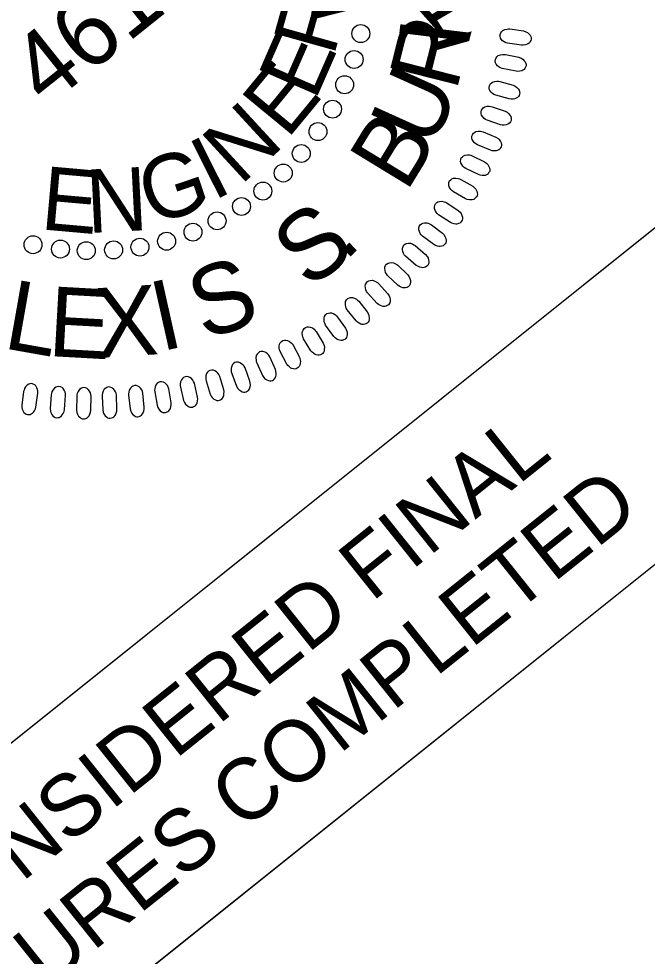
# Model space of a CAD drawing. Extents: x 473546 to 475544, y 505920 to 507827.
# Drawn here: x 474878.2 to 474934.4, y 507600.7 to 507684.5 of the extents above; entities that cross this region are included whole.
import ezdxf

# ---------------------------------------------------------------- set-up
doc = ezdxf.new("R2010")
doc.units = 0
for name, color, linetype in [('Sheet Clip Boundary CELL', 7, 'Continuous'), ('Sheet Plan CELL', 7, 'Continuous'), ('Sheet Profile Grid Minor CELL', 7, 'Continuous'), ('Sheet Sticker Exception Certification CELL', 7, 'Continuous'), ('Sheet Sticker Incomplete CELL', 7, 'Continuous')]:
    doc.layers.add(name, color=color, linetype=linetype)

msp = doc.modelspace()

# ---------------------------------------------------------------- linework, layer by layer
at = {"layer": 'Sheet Clip Boundary CELL'}
msp.add_lwpolyline([(474813.139, 507538.121), (474704.643, 507673.668), (473746.994, 506907.144), (474401.701, 506086.253), (475384.175, 506871.789), (475333.837, 506934.746), (475466.728, 507040.999), (474969.31, 507663.123)], close=True, dxfattribs=at)
at = {"layer": 'Sheet Plan CELL'}
msp.add_lwpolyline([(474806.271, 507706.801), (474884.328, 507769.288), (474954.641, 507681.452), (474876.574, 507618.957)], close=True, dxfattribs=at)
at = {"layer": 'Sheet Profile Grid Minor CELL'}
for points in [[(474922.094, 507683.546), (474923.309, 507683.372), (474923.52, 507683.303), (474923.652, 507683.232), (474923.803, 507683.097), (474923.898, 507682.985), (474923.961, 507682.863), (474923.986, 507682.754), (474923.989, 507682.639), (474923.954, 507682.532), (474923.907, 507682.418), (474923.834, 507682.322), (474923.72, 507682.233), (474923.632, 507682.185), (474923.475, 507682.14), (474923.288, 507682.106), (474923.128, 507682.106), (474921.882, 507682.277), (474921.718, 507682.323), (474921.586, 507682.388), (474921.441, 507682.499), (474921.318, 507682.629), (474921.254, 507682.737), (474921.216, 507682.901), (474921.218, 507683.052), (474921.278, 507683.194), (474921.343, 507683.29), (474921.459, 507683.402), (474921.643, 507683.497), (474921.831, 507683.538), (474921.963, 507683.549)], [(474921.697, 507681.269), (474922.898, 507681.019), (474923.105, 507680.938), (474923.231, 507680.858), (474923.375, 507680.714), (474923.462, 507680.597), (474923.518, 507680.47), (474923.535, 507680.36), (474923.532, 507680.246), (474923.489, 507680.141), (474923.436, 507680.03), (474923.356, 507679.939), (474923.237, 507679.857), (474923.147, 507679.814), (474922.987, 507679.779), (474922.798, 507679.757), (474922.638, 507679.768), (474921.406, 507680.016), (474921.245, 507680.073), (474921.117, 507680.146), (474920.979, 507680.266), (474920.865, 507680.403), (474920.807, 507680.515), (474920.78, 507680.681), (474920.791, 507680.831), (474920.861, 507680.969), (474920.931, 507681.062), (474921.055, 507681.166), (474921.245, 507681.248), (474921.435, 507681.278), (474921.568, 507681.281)], [(474921.187, 507678.855), (474922.37, 507678.53), (474922.571, 507678.436), (474922.693, 507678.35), (474922.826, 507678.197), (474922.906, 507678.073), (474922.954, 507677.944), (474922.964, 507677.833), (474922.953, 507677.719), (474922.905, 507677.617), (474922.844, 507677.509), (474922.76, 507677.424), (474922.635, 507677.35), (474922.542, 507677.313), (474922.38, 507677.287), (474922.191, 507677.278), (474922.032, 507677.298), (474920.818, 507677.623), (474920.66, 507677.69), (474920.538, 507677.771), (474920.407, 507677.899), (474920.302, 507678.044), (474920.251, 507678.159), (474920.235, 507678.326), (474920.256, 507678.476), (474920.334, 507678.609), (474920.409, 507678.697), (474920.539, 507678.793), (474920.734, 507678.863), (474920.926, 507678.881), (474921.058, 507678.875)], [(474920.499, 507676.604), (474921.66, 507676.205), (474921.855, 507676.099), (474921.97, 507676.004), (474922.094, 507675.843), (474922.167, 507675.715), (474922.205, 507675.583), (474922.21, 507675.471), (474922.192, 507675.358), (474922.136, 507675.259), (474922.069, 507675.156), (474921.979, 507675.076), (474921.851, 507675.01), (474921.756, 507674.979), (474921.592, 507674.964), (474921.402, 507674.965), (474921.245, 507674.996), (474920.054, 507675.397), (474919.901, 507675.473), (474919.783, 507675.561), (474919.661, 507675.698), (474919.566, 507675.849), (474919.522, 507675.967), (474919.516, 507676.135), (474919.546, 507676.283), (474919.632, 507676.412), (474919.714, 507676.494), (474919.849, 507676.582), (474920.048, 507676.64), (474920.24, 507676.646), (474920.372, 507676.631)], [(474919.708, 507674.362), (474920.841, 507673.891), (474921.029, 507673.773), (474921.138, 507673.671), (474921.252, 507673.502), (474921.316, 507673.37), (474921.346, 507673.236), (474921.343, 507673.124), (474921.318, 507673.013), (474921.257, 507672.917), (474921.184, 507672.818), (474921.089, 507672.744), (474920.956, 507672.686), (474920.859, 507672.661), (474920.695, 507672.656), (474920.507, 507672.67), (474920.351, 507672.711), (474919.188, 507673.186), (474919.04, 507673.271), (474918.928, 507673.367), (474918.815, 507673.51), (474918.729, 507673.667), (474918.692, 507673.788), (474918.697, 507673.956), (474918.736, 507674.102), (474918.83, 507674.224), (474918.917, 507674.302), (474919.057, 507674.381), (474919.26, 507674.426), (474919.452, 507674.42), (474919.582, 507674.397)], [(474918.731, 507672.218), (474919.833, 507671.677), (474920.013, 507671.547), (474920.115, 507671.439), (474920.219, 507671.263), (474920.274, 507671.128), (474920.296, 507670.992), (474920.286, 507670.88), (474920.254, 507670.77), (474920.187, 507670.679), (474920.107, 507670.585), (474920.008, 507670.517), (474919.872, 507670.468), (474919.774, 507670.448), (474919.61, 507670.454), (474919.423, 507670.48), (474919.269, 507670.53), (474918.138, 507671.077), (474917.996, 507671.172), (474917.89, 507671.274), (474917.787, 507671.424), (474917.711, 507671.586), (474917.682, 507671.709), (474917.697, 507671.876), (474917.746, 507672.02), (474917.847, 507672.136), (474917.938, 507672.208), (474918.083, 507672.278), (474918.288, 507672.311), (474918.48, 507672.292), (474918.609, 507672.261)], [(474917.7, 507670.102), (474918.764, 507669.493), (474918.936, 507669.352), (474919.032, 507669.237), (474919.124, 507669.056), (474919.17, 507668.917), (474919.184, 507668.78), (474919.167, 507668.669), (474919.128, 507668.562), (474919.055, 507668.475), (474918.97, 507668.386), (474918.866, 507668.324), (474918.728, 507668.283), (474918.629, 507668.271), (474918.465, 507668.286), (474918.28, 507668.324), (474918.13, 507668.383), (474917.036, 507669.001), (474916.9, 507669.104), (474916.801, 507669.212), (474916.706, 507669.369), (474916.641, 507669.536), (474916.62, 507669.66), (474916.645, 507669.826), (474916.703, 507669.966), (474916.811, 507670.076), (474916.907, 507670.142), (474917.056, 507670.203), (474917.262, 507670.222), (474917.453, 507670.192), (474917.579, 507670.153)], [(474916.447, 507667.999), (474917.471, 507667.325), (474917.634, 507667.173), (474917.722, 507667.053), (474917.802, 507666.866), (474917.84, 507666.724), (474917.845, 507666.586), (474917.821, 507666.477), (474917.775, 507666.372), (474917.697, 507666.29), (474917.607, 507666.207), (474917.499, 507666.152), (474917.358, 507666.12), (474917.259, 507666.113), (474917.097, 507666.139), (474916.914, 507666.188), (474916.768, 507666.257), (474915.715, 507666.941), (474915.586, 507667.054), (474915.494, 507667.168), (474915.41, 507667.33), (474915.355, 507667.5), (474915.342, 507667.626), (474915.378, 507667.79), (474915.443, 507667.926), (474915.558, 507668.028), (474915.658, 507668.088), (474915.811, 507668.14), (474916.018, 507668.146), (474916.206, 507668.104), (474916.33, 507668.058)], [(474915.076, 507666.043), (474916.057, 507665.305), (474916.21, 507665.144), (474916.29, 507665.018), (474916.358, 507664.826), (474916.388, 507664.683), (474916.384, 507664.545), (474916.353, 507664.438), (474916.301, 507664.336), (474916.218, 507664.259), (474916.122, 507664.181), (474916.012, 507664.133), (474915.869, 507664.109), (474915.77, 507664.11), (474915.609, 507664.146), (474915.43, 507664.206), (474915.289, 507664.284), (474914.28, 507665.033), (474914.158, 507665.153), (474914.074, 507665.273), (474914, 507665.441), (474913.956, 507665.614), (474913.95, 507665.74), (474913.997, 507665.901), (474914.071, 507666.033), (474914.193, 507666.128), (474914.296, 507666.181), (474914.451, 507666.224), (474914.659, 507666.217), (474914.843, 507666.163), (474914.964, 507666.109)], [(474913.628, 507664.195), (474914.56, 507663.396), (474914.703, 507663.226), (474914.775, 507663.096), (474914.831, 507662.9), (474914.851, 507662.755), (474914.839, 507662.617), (474914.801, 507662.512), (474914.743, 507662.414), (474914.655, 507662.342), (474914.555, 507662.271), (474914.441, 507662.23), (474914.297, 507662.215), (474914.198, 507662.221), (474914.041, 507662.268), (474913.865, 507662.339), (474913.729, 507662.425), (474912.77, 507663.237), (474912.656, 507663.364), (474912.578, 507663.489), (474912.516, 507663.661), (474912.482, 507663.836), (474912.485, 507663.963), (474912.541, 507664.12), (474912.624, 507664.247), (474912.751, 507664.334), (474912.857, 507664.382), (474913.015, 507664.414), (474913.222, 507664.394), (474913.403, 507664.329), (474913.52, 507664.267)], [(474912.077, 507662.427), (474912.957, 507661.573), (474913.089, 507661.394), (474913.153, 507661.259), (474913.197, 507661.06), (474913.207, 507660.914), (474913.187, 507660.778), (474913.142, 507660.675), (474913.078, 507660.58), (474912.986, 507660.514), (474912.881, 507660.449), (474912.766, 507660.415), (474912.621, 507660.41), (474912.522, 507660.423), (474912.367, 507660.479), (474912.197, 507660.561), (474912.067, 507660.656), (474911.16, 507661.525), (474911.054, 507661.66), (474910.986, 507661.789), (474910.934, 507661.965), (474910.911, 507662.142), (474910.922, 507662.268), (474910.988, 507662.422), (474911.078, 507662.544), (474911.211, 507662.622), (474911.32, 507662.663), (474911.479, 507662.685), (474911.684, 507662.652), (474911.861, 507662.575), (474911.974, 507662.507)], [(474910.351, 507660.798), (474911.176, 507659.889), (474911.296, 507659.702), (474911.352, 507659.564), (474911.382, 507659.363), (474911.385, 507659.216), (474911.355, 507659.082), (474911.304, 507658.982), (474911.235, 507658.892), (474911.138, 507658.832), (474911.03, 507658.773), (474910.912, 507658.747), (474910.767, 507658.751), (474910.669, 507658.769), (474910.519, 507658.835), (474910.354, 507658.928), (474910.23, 507659.031), (474909.379, 507659.956), (474909.282, 507660.096), (474909.222, 507660.23), (474909.181, 507660.408), (474909.17, 507660.587), (474909.188, 507660.711), (474909.264, 507660.861), (474909.362, 507660.977), (474909.499, 507661.047), (474909.61, 507661.081), (474909.771, 507661.093), (474909.974, 507661.047), (474910.144, 507660.96), (474910.253, 507660.884)], [(474908.58, 507659.223), (474909.346, 507658.265), (474909.453, 507658.071), (474909.5, 507657.929), (474909.519, 507657.726), (474909.511, 507657.58), (474909.473, 507657.447), (474909.417, 507657.351), (474909.341, 507657.266), (474909.242, 507657.211), (474909.129, 507657.16), (474909.01, 507657.14), (474908.866, 507657.154), (474908.769, 507657.179), (474908.624, 507657.253), (474908.465, 507657.356), (474908.348, 507657.467), (474907.557, 507658.443), (474907.469, 507658.59), (474907.417, 507658.727), (474907.387, 507658.907), (474907.387, 507659.086), (474907.413, 507659.21), (474907.499, 507659.355), (474907.603, 507659.464), (474907.745, 507659.526), (474907.858, 507659.552), (474908.019, 507659.554), (474908.218, 507659.496), (474908.383, 507659.397), (474908.487, 507659.315)], [(474906.698, 507657.809), (474907.402, 507656.804), (474907.497, 507656.604), (474907.535, 507656.459), (474907.541, 507656.256), (474907.525, 507656.11), (474907.478, 507655.981), (474907.416, 507655.888), (474907.334, 507655.807), (474907.232, 507655.76), (474907.117, 507655.715), (474906.997, 507655.704), (474906.854, 507655.726), (474906.759, 507655.756), (474906.618, 507655.84), (474906.466, 507655.953), (474906.356, 507656.071), (474905.628, 507657.095), (474905.549, 507657.246), (474905.506, 507657.387), (474905.488, 507657.569), (474905.499, 507657.747), (474905.533, 507657.869), (474905.627, 507658.008), (474905.738, 507658.11), (474905.884, 507658.163), (474905.997, 507658.182), (474906.159, 507658.174), (474906.354, 507658.103), (474906.513, 507657.995), (474906.611, 507657.906)], [(474904.765, 507656.515), (474905.405, 507655.468), (474905.487, 507655.262), (474905.516, 507655.115), (474905.509, 507654.912), (474905.483, 507654.768), (474905.429, 507654.641), (474905.361, 507654.553), (474905.275, 507654.477), (474905.17, 507654.436), (474905.052, 507654.399), (474904.931, 507654.395), (474904.79, 507654.426), (474904.697, 507654.463), (474904.562, 507654.556), (474904.417, 507654.677), (474904.315, 507654.801), (474903.653, 507655.869), (474903.584, 507656.026), (474903.549, 507656.169), (474903.542, 507656.351), (474903.565, 507656.529), (474903.606, 507656.648), (474903.709, 507656.781), (474903.826, 507656.876), (474903.974, 507656.92), (474904.09, 507656.932), (474904.25, 507656.913), (474904.44, 507656.831), (474904.592, 507656.713), (474904.685, 507656.617)], [(474902.714, 507655.291), (474903.287, 507654.206), (474903.357, 507653.995), (474903.376, 507653.847), (474903.356, 507653.645), (474903.321, 507653.503), (474903.259, 507653.38), (474903.185, 507653.295), (474903.095, 507653.226), (474902.987, 507653.191), (474902.867, 507653.161), (474902.747, 507653.165), (474902.608, 507653.205), (474902.518, 507653.247), (474902.388, 507653.348), (474902.251, 507653.479), (474902.157, 507653.609), (474901.564, 507654.717), (474901.504, 507654.878), (474901.479, 507655.022), (474901.483, 507655.205), (474901.517, 507655.381), (474901.566, 507655.497), (474901.676, 507655.622), (474901.8, 507655.71), (474901.95, 507655.744), (474902.066, 507655.749), (474902.225, 507655.721), (474902.41, 507655.627), (474902.554, 507655.499), (474902.64, 507655.399)], [(474899.472, 507653.706), (474899.976, 507652.587), (474900.1, 507652.403), (474900.205, 507652.296), (474900.377, 507652.188), (474900.511, 507652.127), (474900.646, 507652.101), (474900.757, 507652.107), (474900.868, 507652.136), (474900.961, 507652.2), (474901.059, 507652.277), (474901.13, 507652.373), (474901.184, 507652.508), (474901.206, 507652.605), (474901.205, 507652.769), (474901.186, 507652.957), (474901.141, 507653.112), (474900.632, 507654.261), (474900.542, 507654.406), (474900.443, 507654.515), (474900.296, 507654.624), (474900.137, 507654.705), (474900.015, 507654.738), (474899.847, 507654.728), (474899.703, 507654.684), (474899.583, 507654.586), (474899.508, 507654.498), (474899.433, 507654.355), (474899.394, 507654.151), (474899.406, 507653.96), (474899.432, 507653.83)], [(474897.23, 507652.773), (474897.663, 507651.625), (474897.775, 507651.433), (474897.873, 507651.321), (474898.038, 507651.201), (474898.168, 507651.133), (474898.301, 507651.098), (474898.412, 507651.098), (474898.525, 507651.119), (474898.622, 507651.177), (474898.724, 507651.247), (474898.801, 507651.34), (474898.863, 507651.471), (474898.891, 507651.566), (474898.901, 507651.73), (474898.894, 507651.919), (474898.859, 507652.076), (474898.423, 507653.255), (474898.342, 507653.405), (474898.25, 507653.52), (474898.11, 507653.637), (474897.957, 507653.729), (474897.837, 507653.769), (474897.669, 507653.77), (474897.522, 507653.736), (474897.396, 507653.646), (474897.316, 507653.562), (474897.232, 507653.424), (474897.181, 507653.224), (474897.181, 507653.031), (474897.199, 507652.9)], [(474894.942, 507652.098), (474895.302, 507650.925), (474895.402, 507650.726), (474895.492, 507650.607), (474895.65, 507650.478), (474895.775, 507650.402), (474895.906, 507650.359), (474896.017, 507650.351), (474896.131, 507650.365), (474896.231, 507650.417), (474896.337, 507650.481), (474896.42, 507650.568), (474896.49, 507650.695), (474896.524, 507650.788), (474896.544, 507650.951), (474896.549, 507651.14), (474896.524, 507651.299), (474896.162, 507652.503), (474896.092, 507652.658), (474896.007, 507652.778), (474895.875, 507652.905), (474895.727, 507653.005), (474895.61, 507653.053), (474895.443, 507653.065), (474895.293, 507653.04), (474895.163, 507652.957), (474895.078, 507652.879), (474894.985, 507652.747), (474894.921, 507652.549), (474894.909, 507652.358), (474894.919, 507652.226)], [(474892.651, 507651.555), (474892.936, 507650.362), (474893.024, 507650.158), (474893.107, 507650.034), (474893.256, 507649.895), (474893.376, 507649.811), (474893.503, 507649.76), (474893.614, 507649.745), (474893.728, 507649.752), (474893.832, 507649.798), (474893.942, 507649.854), (474894.029, 507649.936), (474894.108, 507650.058), (474894.148, 507650.15), (474894.179, 507650.311), (474894.195, 507650.499), (474894.18, 507650.66), (474893.895, 507651.883), (474893.833, 507652.043), (474893.757, 507652.168), (474893.633, 507652.303), (474893.491, 507652.413), (474893.378, 507652.467), (474893.211, 507652.489), (474893.061, 507652.474), (474892.925, 507652.4), (474892.835, 507652.327), (474892.735, 507652.201), (474892.658, 507652.009), (474892.635, 507651.817), (474892.636, 507651.685)], [(474878.642, 507651.159), (474878.468, 507649.944), (474878.474, 507649.722), (474878.505, 507649.576), (474878.592, 507649.392), (474878.673, 507649.27), (474878.773, 507649.175), (474878.871, 507649.121), (474878.979, 507649.085), (474879.093, 507649.089), (474879.216, 507649.102), (474879.327, 507649.146), (474879.445, 507649.231), (474879.516, 507649.3), (474879.604, 507649.439), (474879.688, 507649.609), (474879.733, 507649.763), (474879.919, 507651.006), (474879.921, 507651.177), (474879.895, 507651.322), (474879.83, 507651.492), (474879.739, 507651.646), (474879.654, 507651.739), (474879.507, 507651.821), (474879.361, 507651.861), (474879.208, 507651.843), (474879.097, 507651.808), (474878.957, 507651.728), (474878.815, 507651.577), (474878.723, 507651.409), (474878.675, 507651.285)], [(474881.108, 507650.855), (474881.011, 507649.632), (474881.03, 507649.41), (474881.071, 507649.267), (474881.17, 507649.089), (474881.258, 507648.971), (474881.363, 507648.883), (474881.464, 507648.836), (474881.575, 507648.807), (474881.688, 507648.818), (474881.81, 507648.838), (474881.919, 507648.889), (474882.031, 507648.981), (474882.097, 507649.055), (474882.176, 507649.199), (474882.249, 507649.373), (474882.285, 507649.53), (474882.392, 507650.783), (474882.383, 507650.953), (474882.349, 507651.096), (474882.272, 507651.262), (474882.172, 507651.41), (474882.081, 507651.497), (474881.93, 507651.57), (474881.781, 507651.601), (474881.63, 507651.573), (474881.521, 507651.532), (474881.387, 507651.443), (474881.254, 507651.283), (474881.173, 507651.109), (474881.133, 507650.982)], [(474883.383, 507650.716), (474883.363, 507649.489), (474883.397, 507649.269), (474883.446, 507649.129), (474883.556, 507648.957), (474883.652, 507648.846), (474883.762, 507648.764), (474883.866, 507648.722), (474883.978, 507648.701), (474884.09, 507648.719), (474884.21, 507648.747), (474884.316, 507648.805), (474884.422, 507648.904), (474884.484, 507648.982), (474884.553, 507649.13), (474884.616, 507649.309), (474884.641, 507649.468), (474884.669, 507650.724), (474884.65, 507650.894), (474884.606, 507651.035), (474884.52, 507651.196), (474884.411, 507651.337), (474884.314, 507651.419), (474884.158, 507651.481), (474884.009, 507651.503), (474883.859, 507651.466), (474883.753, 507651.417), (474883.625, 507651.32), (474883.503, 507651.153), (474883.432, 507650.974), (474883.4, 507650.845)], [(474885.649, 507650.735), (474885.706, 507649.51), (474885.753, 507649.293), (474885.812, 507649.155), (474885.932, 507648.991), (474886.035, 507648.886), (474886.15, 507648.811), (474886.256, 507648.776), (474886.369, 507648.762), (474886.48, 507648.787), (474886.598, 507648.823), (474886.7, 507648.887), (474886.8, 507648.992), (474886.856, 507649.073), (474886.916, 507649.227), (474886.968, 507649.408), (474886.983, 507649.569), (474886.932, 507650.824), (474886.902, 507650.993), (474886.85, 507651.13), (474886.754, 507651.285), (474886.636, 507651.42), (474886.535, 507651.495), (474886.375, 507651.548), (474886.224, 507651.561), (474886.077, 507651.514), (474885.975, 507651.459), (474885.852, 507651.354), (474885.741, 507651.179), (474885.682, 507650.996), (474885.658, 507650.865)], [(474888.017, 507650.821), (474888.151, 507649.601), (474888.211, 507649.387), (474888.278, 507649.254), (474888.408, 507649.097), (474888.517, 507648.999), (474888.637, 507648.932), (474888.745, 507648.903), (474888.859, 507648.896), (474888.968, 507648.928), (474889.084, 507648.97), (474889.181, 507649.042), (474889.275, 507649.152), (474889.326, 507649.238), (474889.376, 507649.394), (474889.416, 507649.579), (474889.421, 507649.74), (474889.291, 507650.99), (474889.25, 507651.156), (474889.191, 507651.29), (474889.084, 507651.439), (474888.958, 507651.565), (474888.852, 507651.634), (474888.69, 507651.677), (474888.539, 507651.68), (474888.395, 507651.624), (474888.296, 507651.563), (474888.18, 507651.451), (474888.08, 507651.269), (474888.033, 507651.082), (474888.017, 507650.951)], [(474890.352, 507651.132), (474890.562, 507649.924), (474890.636, 507649.714), (474890.711, 507649.585), (474890.851, 507649.437), (474890.965, 507649.345), (474891.09, 507649.286), (474891.199, 507649.265), (474891.314, 507649.265), (474891.42, 507649.303), (474891.533, 507649.353), (474891.626, 507649.43), (474891.712, 507649.546), (474891.757, 507649.635), (474891.798, 507649.794), (474891.826, 507649.981), (474891.821, 507650.142), (474891.613, 507651.382), (474891.562, 507651.544), (474891.493, 507651.675), (474891.378, 507651.816), (474891.244, 507651.935), (474891.135, 507651.997), (474890.97, 507652.029), (474890.819, 507652.023), (474890.679, 507651.958), (474890.584, 507651.891), (474890.476, 507651.771), (474890.387, 507651.584), (474890.351, 507651.395), (474890.344, 507651.263)]]:
    msp.add_lwpolyline(points, close=True, dxfattribs=at)
for centre in [(474908.767, 507683.135), (474908.17, 507680.821), (474907.325, 507678.564), (474906.241, 507676.386), (474904.941, 507674.378), (474903.449, 507672.419), (474901.839, 507670.672), (474900.017, 507669.062), (474898.108, 507667.688), (474895.925, 507666.401), (474893.773, 507665.394), (474879.481, 507664.268), (474881.932, 507663.882), (474886.683, 507663.805), (474889.034, 507664.053), (474891.416, 507664.581), (474884.239, 507663.738)]:
    msp.add_circle(centre, 0.801, dxfattribs=at)
at = {"layer": 'Sheet Sticker Exception Certification CELL'}
for p, q in [((474798.455, 507556.468), (474954.633, 507681.462)), ((474798.455, 507556.468), (474954.633, 507681.462)), ((474969.317, 507663.114), (474813.139, 507538.121)), ((474969.317, 507663.114), (474813.139, 507538.121))]:
    msp.add_line(p, q, dxfattribs=at)

# ---------------------------------------------------------------- texts
at = {"layer": 'Sheet Profile Grid Minor CELL'}
for s, height, rotation, p in [('46155', 6.2363, 38.65259, (474880.691, 507676.479)), ('K', 6.236, 83.09383, (474918.319, 507681.766)), ('R', 5.669, 74.33479, (474906.337, 507681.015)), ('R', 6.236, 75.8188, (474917.291, 507677.879)), ('E', 5.669, 66.39499, (474904.674, 507677.042)), ('E', 5.669, 50.51539, (474902.198, 507673.622)), ('U', 6.236, 65.71895, (474915.129, 507672.732)), ('N', 5.669, 42.5756, (474898.011, 507669.494)), ('B', 6.236, 58.60211, (474912.822, 507668.861)), ('I', 5.669, 26.696, (474895.566, 507668.143)), ('G', 5.669, 18.7562, (474890.116, 507665.945)), ('E', 5.669, 354.93681, (474880.064, 507665.654)), ('N', 5.669, 2.87661, (474884.359, 507665.306)), ('S', 6.236, 38.05384, (474904.139, 507660.185)), ('.', 6.236, 44.8995, (474907.323, 507662.671)), ('S', 6.236, 19.45864, (474894.785, 507655.675)), ('L', 6.236, 349.97435, (474876.696, 507655.041)), ('E', 6.236, 356.82, (474880.74, 507654.33)), ('X', 6.236, 3.66566, (474885.253, 507654.135)), ('I', 6.236, 12.61298, (474890.873, 507654.713))]:
    msp.add_text(s, height=height, rotation=rotation, dxfattribs=at).set_placement(p)
at = {"layer": 'Sheet Sticker Exception Certification CELL'}
for s, p in [('DOCUMENT NOT CONSIDERED FINAL', (474821.37, 507561.557)), ('DOCUMENT NOT CONSIDERED FINAL', (474821.37, 507561.557)), ('UNLESS ALL SIGNATURES COMPLETED', (474822.91, 507551.518)), ('UNLESS ALL SIGNATURES COMPLETED', (474822.91, 507551.518))]:
    msp.add_text(s, height=5.5, rotation=38.67122, dxfattribs=at).set_placement(p)
at = {"layer": 'Sheet Sticker Incomplete CELL'}
for s, height, p in [('INCOMPLETE PLANS', 11.52, (474783.711, 507631.684)), ('DO NOT USE FOR R/W ACQUISITION', 5.76, (474790.591, 507628.289))]:
    msp.add_text(s, height=height, rotation=38.67122, dxfattribs=at).set_placement(p)

doc.saveas('drawing.dxf')
